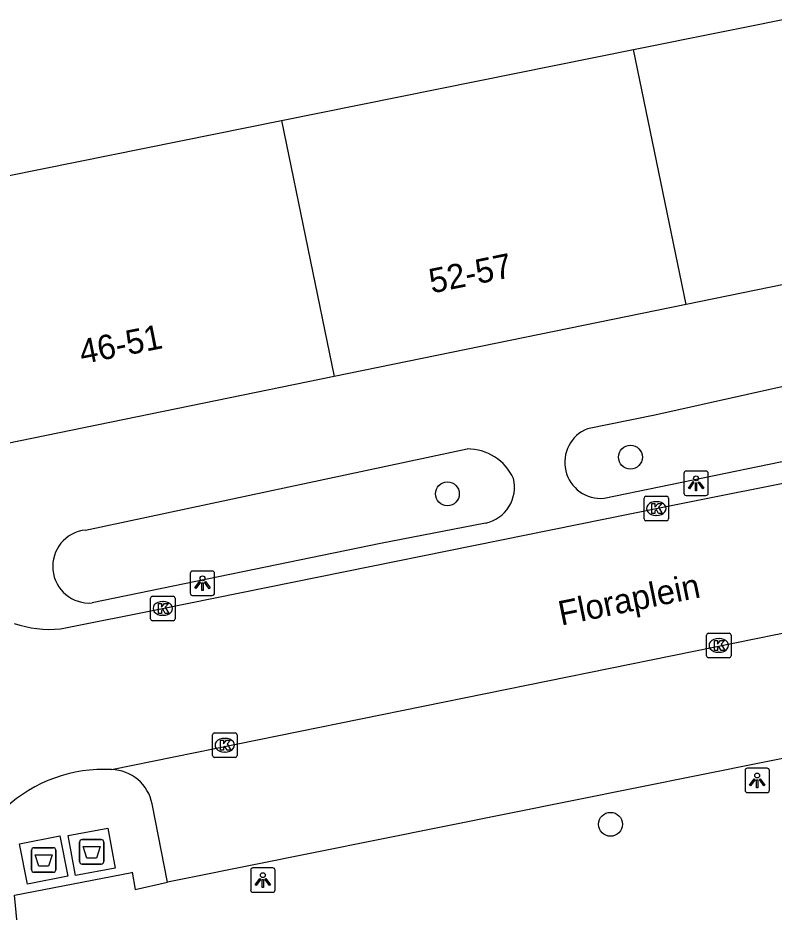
# Model space of a CAD drawing. Extents: x 162250 to 162654, y 380744 to 381605.
# Drawn here: x 162562.39 to 162593.35, y 380831.58 to 380868.17 of the extents above; entities that cross this region are included whole.
import ezdxf

# ---------------------------------------------------------------- set-up
doc = ezdxf.new("R2010")
doc.units = 0
for name, color, linetype in [('IMGEO_Afval_apart_plaats', 7, 'Continuous'), ('IMGEO_Boom', 7, 'Continuous'), ('IMGEO_Fietspad_gesloten', 7, 'Continuous'), ('IMGEO_Kolk', 7, 'Continuous'), ('IMGEO_Lichtpunt', 7, 'Continuous'), ('IMGEO_Openbare_ruimte_label', 7, 'Continuous'), ('IMGEO_Pand', 7, 'Continuous'), ('IMGEO_Pand_nummerreeks', 7, 'Continuous'), ('IMGEO_Parkeervlak_open', 7, 'Continuous'), ('IMGEO_Rijbaan_lokaal_open', 7, 'Continuous'), ('IMGEO_Voetpad_gesloten', 7, 'Continuous'), ('IMGEO_Voetpad_open', 7, 'Continuous')]:
    doc.layers.add(name, color=color, linetype=linetype)

msp = doc.modelspace()

# ---------------------------------------------------------------- linework, layer by layer
at = {"layer": 'IMGEO_Afval_apart_plaats'}
for p, q in [((162564.916, 380833.652), (162564.916, 380834.452)), ((162564.916, 380834.452), (162564.916, 380833.652)), ((162565.016, 380834.552), (162565.806, 380834.552)), ((162565.806, 380834.552), (162565.016, 380834.552)), ((162565.906, 380834.452), (162565.906, 380833.652)), ((162565.906, 380833.652), (162565.906, 380834.452)), ((162562.951, 380833.317), (162562.951, 380834.117)), ((162562.951, 380834.117), (162562.951, 380833.317)), ((162563.051, 380834.217), (162563.841, 380834.217)), ((162563.841, 380834.217), (162563.051, 380834.217)), ((162563.941, 380834.117), (162563.941, 380833.317)), ((162563.941, 380833.317), (162563.941, 380834.117)), ((162565.806, 380833.552), (162565.016, 380833.552)), ((162565.016, 380833.552), (162565.806, 380833.552)), ((162563.841, 380833.217), (162563.051, 380833.217)), ((162563.051, 380833.217), (162563.841, 380833.217))]:
    msp.add_line(p, q, dxfattribs=at)
for points in [[(162565.059, 380834.266), (162565.763, 380834.266), (162565.614, 380833.796), (162565.208, 380833.796), (162565.059, 380834.266)], [(162563.094, 380833.931), (162563.798, 380833.931), (162563.649, 380833.461), (162563.243, 380833.461), (162563.094, 380833.931)]]:
    msp.add_lwpolyline(points, dxfattribs=at)
for centre, start, end in [((162565.016, 380834.452), 90, 180), ((162565.016, 380834.452), 90, 180), ((162565.806, 380834.452), 0, 90), ((162565.806, 380834.452), 360, 90), ((162563.051, 380834.117), 90, 180), ((162563.051, 380834.117), 90, 180), ((162563.841, 380834.117), 0, 90), ((162563.841, 380834.117), 360, 90), ((162565.016, 380833.652), 180, 270), ((162565.016, 380833.652), 180, 270), ((162565.806, 380833.652), 270, 0), ((162565.806, 380833.652), 270, 0), ((162563.051, 380833.317), 180, 270), ((162563.051, 380833.317), 180, 270), ((162563.841, 380833.317), 270, 0), ((162563.841, 380833.317), 270, 0)]:
    msp.add_arc(centre, 0.1, start, end, dxfattribs=at)
at = {"layer": 'IMGEO_Boom'}
for centre in [(162587.464, 380850.195), (162579.972, 380848.697), (162586.65, 380835.177)]:
    msp.add_circle(centre, 0.489, dxfattribs=at)
at = {"layer": 'IMGEO_Fietspad_gesloten'}
msp.add_lwpolyline([(162564.447, 380834.719), (162566.075, 380835.017), (162566.374, 380833.385), (162564.746, 380833.087), (162564.447, 380834.719)], dxfattribs=at)
at = {"layer": 'IMGEO_Kolk'}
for p, q in [((162588.024, 380847.67), (162588.024, 380848.522)), ((162588.099, 380848.596), (162588.951, 380848.596)), ((162588.512, 380848.376), (162588.537, 380848.376)), ((162589.025, 380848.522), (162589.025, 380847.67)), ((162588.951, 380847.596), (162588.099, 380847.596)), ((162588.535, 380847.816), (162588.51, 380847.816)), ((162567.824, 380843.581), (162567.824, 380844.433)), ((162567.899, 380844.507), (162568.751, 380844.507)), ((162568.312, 380844.287), (162568.337, 380844.287)), ((162568.825, 380844.433), (162568.825, 380843.581)), ((162568.751, 380843.507), (162567.899, 380843.507)), ((162568.335, 380843.727), (162568.31, 380843.727)), ((162590.581, 380842.067), (162590.581, 380842.919)), ((162590.656, 380842.993), (162591.508, 380842.993)), ((162591.069, 380842.773), (162591.094, 380842.773)), ((162591.582, 380842.919), (162591.582, 380842.067)), ((162591.092, 380842.213), (162591.067, 380842.213)), ((162591.508, 380841.993), (162590.656, 380841.993)), ((162570.36, 380837.987), (162570.36, 380838.839)), ((162570.435, 380838.913), (162571.287, 380838.913)), ((162571.361, 380838.839), (162571.361, 380837.987)), ((162570.848, 380838.693), (162570.873, 380838.693)), ((162570.871, 380838.133), (162570.846, 380838.133)), ((162571.287, 380837.913), (162570.435, 380837.913))]:
    msp.add_line(p, q, dxfattribs=at)
for points in [[(162588.024, 380847.67), (162588.024, 380848.522)], [(162588.099, 380848.596), (162588.951, 380848.596)], [(162588.345, 380848.296), (162588.468, 380848.296), (162588.468, 380848.145), (162588.598, 380848.296), (162588.762, 380848.296), (162588.616, 380848.145), (162588.769, 380847.896), (162588.617, 380847.896), (162588.532, 380848.06), (162588.468, 380847.993), (162588.468, 380847.896), (162588.345, 380847.896), (162588.345, 380848.296)], [(162589.025, 380848.522), (162589.025, 380847.67)], [(162588.951, 380847.596), (162588.099, 380847.596)], [(162567.824, 380843.581), (162567.824, 380844.433)], [(162567.899, 380844.507), (162568.751, 380844.507)], [(162568.825, 380844.433), (162568.825, 380843.581)], [(162568.145, 380844.207), (162568.268, 380844.207), (162568.268, 380844.056), (162568.398, 380844.207), (162568.562, 380844.207), (162568.416, 380844.056), (162568.569, 380843.807), (162568.417, 380843.807), (162568.332, 380843.971), (162568.268, 380843.904), (162568.268, 380843.807), (162568.145, 380843.807), (162568.145, 380844.207)], [(162568.751, 380843.507), (162567.899, 380843.507)], [(162590.581, 380842.067), (162590.581, 380842.919)], [(162590.656, 380842.993), (162591.508, 380842.993)], [(162591.582, 380842.919), (162591.582, 380842.067)], [(162590.902, 380842.693), (162591.025, 380842.693), (162591.025, 380842.542), (162591.155, 380842.693), (162591.319, 380842.693), (162591.173, 380842.542), (162591.326, 380842.293), (162591.174, 380842.293), (162591.089, 380842.457), (162591.025, 380842.39), (162591.025, 380842.293), (162590.902, 380842.293), (162590.902, 380842.693)], [(162591.508, 380841.993), (162590.656, 380841.993)], [(162570.36, 380837.987), (162570.36, 380838.839)], [(162570.435, 380838.913), (162571.287, 380838.913)], [(162571.361, 380838.839), (162571.361, 380837.987)], [(162570.681, 380838.613), (162570.804, 380838.613), (162570.804, 380838.462), (162570.934, 380838.613), (162571.098, 380838.613), (162570.952, 380838.462), (162571.105, 380838.213), (162570.953, 380838.213), (162570.868, 380838.377), (162570.804, 380838.31), (162570.804, 380838.213), (162570.681, 380838.213), (162570.681, 380838.613)], [(162571.287, 380837.913), (162570.435, 380837.913)]]:
    msp.add_lwpolyline(points, dxfattribs=at)
for centre, start, end in [((162588.101, 380848.52), 91.552, 178.448), ((162588.101, 380848.52), 91.552, 178.448), ((162588.949, 380848.52), 1.552, 88.448), ((162588.949, 380848.52), 1.552, 88.448), ((162588.101, 380847.672), 181.552, 268.448), ((162588.101, 380847.672), 181.552, 268.448), ((162588.949, 380847.672), 271.552, 358.448), ((162588.949, 380847.672), 271.552, 358.448), ((162567.901, 380844.431), 91.552, 178.448), ((162567.901, 380844.431), 91.552, 178.448), ((162568.749, 380844.431), 1.552, 88.448), ((162568.749, 380844.431), 1.552, 88.448), ((162567.901, 380843.583), 181.552, 268.448), ((162567.901, 380843.583), 181.552, 268.448), ((162568.749, 380843.583), 271.552, 358.448), ((162568.749, 380843.583), 271.552, 358.448), ((162590.658, 380842.917), 91.552, 178.448), ((162590.658, 380842.917), 91.552, 178.448), ((162591.506, 380842.917), 1.552, 88.448), ((162591.506, 380842.917), 1.552, 88.448), ((162590.658, 380842.069), 181.552, 268.448), ((162590.658, 380842.069), 181.552, 268.448), ((162591.506, 380842.069), 271.552, 358.448), ((162591.506, 380842.069), 271.552, 358.448), ((162570.437, 380838.837), 91.552, 178.448), ((162570.437, 380838.837), 91.552, 178.448), ((162571.285, 380838.837), 1.552, 88.448), ((162571.285, 380838.837), 1.552, 88.448), ((162570.437, 380837.989), 181.552, 268.448), ((162570.437, 380837.989), 181.552, 268.448), ((162571.285, 380837.989), 271.552, 358.448), ((162571.285, 380837.989), 271.552, 358.448)]:
    msp.add_arc(centre, 0.0765, start, end, dxfattribs=at)
for centre, major_axis, ratio, start_param, end_param in [((162588.511, 380848.096), (-0.387, 0.002), 0.722429, 4.712389, 7.853982), ((162588.536, 380848.096), (-0.39, 0.002), 0.717154, 1.570796, 4.712389), ((162568.311, 380844.007), (-0.387, 0.002), 0.722429, 4.712389, 7.853982), ((162568.336, 380844.007), (-0.39, 0.002), 0.717154, 1.570796, 4.712389), ((162591.068, 380842.493), (-0.387, 0.002), 0.722429, 4.712389, 7.853982), ((162591.093, 380842.493), (-0.39, 0.002), 0.717154, 1.570796, 4.712389), ((162570.847, 380838.413), (-0.387, 0.002), 0.722429, 4.712389, 7.853982), ((162570.872, 380838.413), (-0.39, 0.002), 0.717154, 1.570796, 4.712389)]:
    msp.add_ellipse(centre, major_axis=major_axis, ratio=ratio, start_param=start_param, end_param=end_param, dxfattribs=at)
at = {"layer": 'IMGEO_Lichtpunt'}
for p, q in [((162589.653, 380849.531), (162589.653, 380848.724)), ((162589.653, 380849.531), (162589.653, 380848.724)), ((162590.555, 380849.626), (162589.747, 380849.626)), ((162590.555, 380849.626), (162589.747, 380849.626)), ((162590.649, 380848.724), (162590.649, 380849.531)), ((162590.649, 380848.724), (162590.649, 380849.531)), ((162589.747, 380848.63), (162590.555, 380848.63)), ((162589.747, 380848.63), (162590.555, 380848.63)), ((162569.447, 380845.443), (162569.447, 380844.636)), ((162569.447, 380845.443), (162569.447, 380844.636)), ((162570.349, 380845.538), (162569.541, 380845.538)), ((162570.349, 380845.538), (162569.541, 380845.538)), ((162570.443, 380844.636), (162570.443, 380845.443)), ((162570.443, 380844.636), (162570.443, 380845.443)), ((162569.541, 380844.542), (162570.349, 380844.542)), ((162569.541, 380844.542), (162570.349, 380844.542)), ((162592.156, 380837.378), (162592.156, 380836.571)), ((162592.156, 380837.378), (162592.156, 380836.571)), ((162593.058, 380837.473), (162592.25, 380837.473)), ((162593.058, 380837.473), (162592.25, 380837.473)), ((162593.152, 380836.571), (162593.152, 380837.378)), ((162593.152, 380836.571), (162593.152, 380837.378)), ((162592.25, 380836.477), (162593.058, 380836.477)), ((162592.25, 380836.477), (162593.058, 380836.477)), ((162571.92, 380833.297), (162571.92, 380832.49)), ((162571.92, 380833.297), (162571.92, 380832.49)), ((162572.822, 380833.392), (162572.014, 380833.392)), ((162572.822, 380833.392), (162572.014, 380833.392)), ((162572.916, 380832.49), (162572.916, 380833.297)), ((162572.916, 380832.49), (162572.916, 380833.297)), ((162572.014, 380832.396), (162572.822, 380832.396)), ((162572.014, 380832.396), (162572.822, 380832.396))]:
    msp.add_line(p, q, dxfattribs=at)
for points in [[(162590.027, 380849.195), (162590.066, 380849.167), (162589.878, 380848.905), (162589.84, 380848.932), (162590.027, 380849.195)], [(162590.129, 380849.147), (162590.176, 380849.147), (162590.176, 380848.825), (162590.129, 380848.825), (162590.129, 380849.147)], [(162590.239, 380849.167), (162590.277, 380849.194), (162590.464, 380848.932), (162590.425, 380848.904), (162590.239, 380849.167)], [(162569.821, 380845.107), (162569.86, 380845.079), (162569.672, 380844.817), (162569.634, 380844.844), (162569.821, 380845.107)], [(162569.923, 380845.059), (162569.97, 380845.059), (162569.97, 380844.737), (162569.923, 380844.737), (162569.923, 380845.059)], [(162570.033, 380845.079), (162570.071, 380845.106), (162570.258, 380844.844), (162570.219, 380844.816), (162570.033, 380845.079)], [(162592.53, 380837.042), (162592.569, 380837.014), (162592.381, 380836.752), (162592.343, 380836.779), (162592.53, 380837.042)], [(162592.632, 380836.994), (162592.679, 380836.994), (162592.679, 380836.672), (162592.632, 380836.672), (162592.632, 380836.994)], [(162592.742, 380837.014), (162592.78, 380837.041), (162592.967, 380836.779), (162592.928, 380836.751), (162592.742, 380837.014)], [(162572.294, 380832.961), (162572.333, 380832.933), (162572.145, 380832.671), (162572.107, 380832.698), (162572.294, 380832.961)], [(162572.396, 380832.913), (162572.443, 380832.913), (162572.443, 380832.591), (162572.396, 380832.591), (162572.396, 380832.913)], [(162572.506, 380832.933), (162572.544, 380832.96), (162572.731, 380832.698), (162572.692, 380832.67), (162572.506, 380832.933)]]:
    msp.add_lwpolyline(points, dxfattribs=at)
for centre in [(162590.152, 380849.329), (162569.946, 380845.241), (162592.655, 380837.176), (162572.419, 380833.095)]:
    msp.add_circle(centre, 0.0994, dxfattribs=at)
for centre, start, end in [((162589.747, 380849.531), 90, 180), ((162589.747, 380849.531), 90, 180), ((162590.555, 380849.531), 0, 90), ((162590.555, 380849.531), 0, 90), ((162589.747, 380848.724), 180, 270), ((162589.747, 380848.724), 180, 270), ((162590.555, 380848.724), 270, 0), ((162590.555, 380848.724), 270, 360), ((162569.541, 380845.443), 90, 180), ((162569.541, 380845.443), 90, 180), ((162570.349, 380845.443), 0, 90), ((162570.349, 380845.443), 0, 90), ((162569.541, 380844.636), 180, 270), ((162569.541, 380844.636), 180, 270), ((162570.349, 380844.636), 270, 0), ((162570.349, 380844.636), 270, 360), ((162592.25, 380837.378), 90, 180), ((162592.25, 380837.378), 90, 180), ((162593.058, 380837.378), 0, 90), ((162593.058, 380837.378), 0, 90), ((162592.25, 380836.571), 180, 270), ((162592.25, 380836.571), 180, 270), ((162593.058, 380836.571), 270, 0), ((162593.058, 380836.571), 270, 360), ((162572.014, 380833.297), 90, 180), ((162572.014, 380833.297), 90, 180), ((162572.822, 380833.297), 0, 90), ((162572.822, 380833.297), 0, 90), ((162572.014, 380832.49), 180, 270), ((162572.014, 380832.49), 180, 270), ((162572.822, 380832.49), 270, 0), ((162572.822, 380832.49), 270, 360)]:
    msp.add_arc(centre, 0.0946, start, end, dxfattribs=at)
at = {"layer": 'IMGEO_Pand'}
for points in [[(162587.591, 380866.878), (162602.001, 380869.784)], [(162573.181, 380863.972), (162587.591, 380866.878)], [(162589.741, 380856.447), (162587.591, 380866.878)], [(162558.618, 380861.185), (162559.157, 380861.297), (162559.187, 380861.15), (162573.181, 380863.972)], [(162573.181, 380863.972), (162575.34, 380853.499)], [(162604.143, 380859.394), (162589.741, 380856.447)], [(162589.741, 380856.447), (162575.34, 380853.499)], [(162575.34, 380853.499), (162561.354, 380850.637), (162561.385, 380850.49), (162560.85, 380850.377)]]:
    msp.add_lwpolyline(points, dxfattribs=at)
at = {"layer": 'IMGEO_Parkeervlak_open'}
msp.add_lwpolyline([(162595.594, 380838.244), (162569.268, 380832.961), (162568.517, 380832.81)], dxfattribs=at)
at = {"layer": 'IMGEO_Rijbaan_lokaal_open'}
for points in [[(162564.132, 380843.173), (162568.317, 380844.003), (162588.525, 380848.096), (162595.697, 380849.533)], [(162566.221, 380837.416), (162594.293, 380843.113)]]:
    msp.add_lwpolyline(points, dxfattribs=at)
for centre, radius, start, end in [((162563.698, 380847.696), 4.544, 251.2257, 275.4774), ((162565.916, 380831.452), 5.972, 87.0761, 178.1405)]:
    msp.add_arc(centre, radius, start, end, dxfattribs=at)
at = {"layer": 'IMGEO_Voetpad_gesloten'}
msp.add_lwpolyline([(162562.46, 380834.381), (162564.107, 380834.705), (162564.432, 380833.053), (162562.785, 380832.729), (162562.46, 380834.381)], dxfattribs=at)
at = {"layer": 'IMGEO_Voetpad_open'}
for points in [[(162597.818, 380853.999), (162588.47, 380851.918), (162585.709, 380851.358)], [(162586.391, 380848.516), (162595.392, 380850.372), (162598.958, 380851.134)], [(162565.153, 380847.215), (162580.78, 380850.533)], [(162581.533, 380847.5), (162577.237, 380846.661), (162565.438, 380844.233)], [(162568.517, 380832.81), (162567.888, 380836.009)], [(162567.473, 380781.301), (162567.093, 380785.029), (162562.571, 380829.016), (162562.247, 380832.277), (162567.053, 380833.21), (162567.066, 380833.212), (162567.19, 380832.512), (162568.517, 380832.81)]]:
    msp.add_lwpolyline(points, dxfattribs=at)
for centre, radius, start, end in [((162586.251, 380849.985), 1.476, 111.5533, 275.4352), ((162580.797, 380848.47), 2.063, 24.4146, 90.4671), ((162581.222, 380848.964), 1.497, 281.9915, 13.8791), ((162565.316, 380845.726), 1.498, 96.2509, 274.6679), ((162566.179, 380835.675), 1.741, 11.0507, 88.6185)]:
    msp.add_arc(centre, radius, start, end, dxfattribs=at)

# ---------------------------------------------------------------- texts
at = {"layer": 'IMGEO_Openbare_ruimte_label'}
msp.add_text('Floraplein', height=1, rotation=11.4785, dxfattribs=at).set_placement((162584.627, 380843.302))
at = {"layer": 'IMGEO_Pand_nummerreeks'}
for s, rotation, p in [('52-57', 11.502, (162579.332, 380856.892)), ('46-51', 11.2149, (162565.015, 380853.997))]:
    msp.add_text(s, height=1, rotation=rotation, dxfattribs=at).set_placement(p)

doc.saveas('drawing.dxf')
